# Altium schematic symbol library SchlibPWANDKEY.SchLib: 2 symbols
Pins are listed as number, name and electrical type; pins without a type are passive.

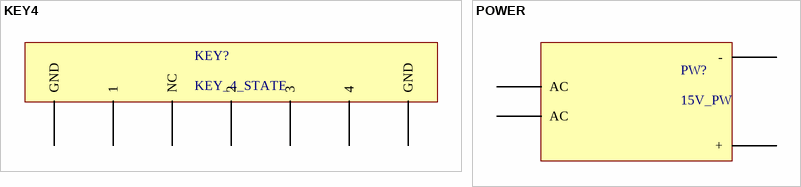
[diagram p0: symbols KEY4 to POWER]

## KEY4
designator KEY?, comment KEY_4_STATE
footprint KEY4
pins: 1, 2, 3, 4, GND, GND, NC

## POWER
designator PW?, comment 15V_PW
footprint POW
pins: 1 AC, 2 AC, 3 -, 4 +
